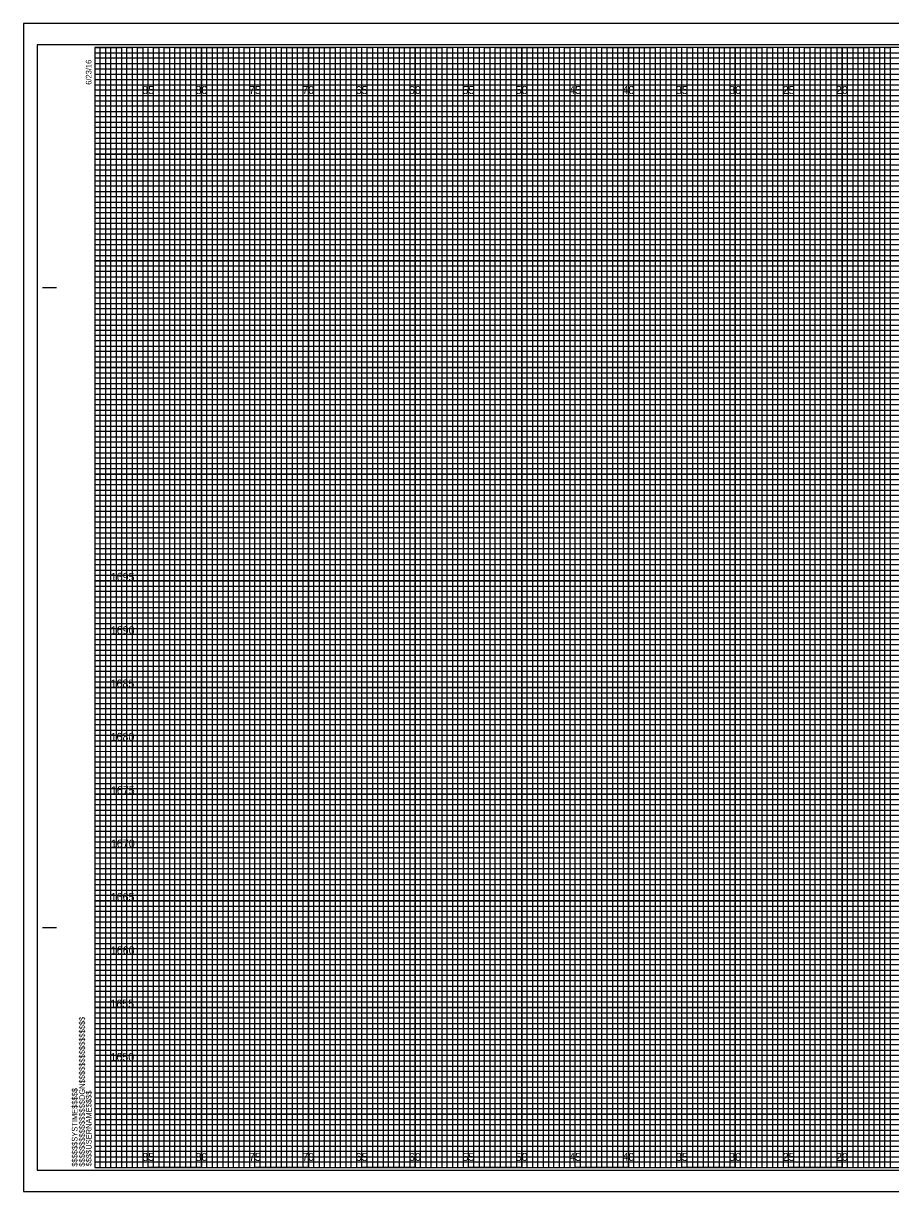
# Model space of a CAD drawing. Extents: x 172 to 723, y -2 to 439.
# Drawn here: x 541.5 to 622.8, y 219.3 to 328.8 of the extents above; entities that cross this region are included whole.
import ezdxf

# ---------------------------------------------------------------- set-up
doc = ezdxf.new("R2010")
doc.units = 0
for name, color, linetype in [('Prop XS Elevation Labels', 7, 'Continuous'), ('Prop XS Offset Labels', 7, 'Continuous'), ('Sheet Cross Section CELL', 7, 'Continuous'), ('Sheet Cross Section Grid Major CELL', 7, 'Continuous'), ('Sheet Cross Section Grid Middle CELL', 7, 'Continuous'), ('Sheet Cross Section Grid Minor 1 CELL', 7, 'Continuous'), ('Sheet Cross Section Grid Minor 2 CELL', 7, 'Continuous'), ('Sheet Cutting Line CELL', 7, 'Continuous'), ('Sheet DOT Grid CELL', 7, 'Continuous'), ('Sheet Plot Border Inside CELL', 7, 'Continuous'), ('Sheet Plot Border Outside CELL', 7, 'Continuous')]:
    doc.layers.add(name, color=color, linetype=linetype)

msp = doc.modelspace()

# ---------------------------------------------------------------- linework, layer by layer
at = {"layer": 'Sheet Cross Section CELL'}
for p, q in [((543.31, 304.07), (544.56, 304.07)), ((543.36, 304.07), (544.61, 304.07)), ((543.31, 244.07), (544.56, 244.07)), ((543.36, 244.07), (544.61, 244.07)), ((548.21, 221.57), (548.21, 221.57)), ((548.21, 221.57), (548.21, 221.57)), ((548.21, 221.57), (548.21, 221.57)), ((548.21, 221.57), (548.21, 221.57)), ((548.21, 221.57), (548.21, 221.57)), ((548.21, 221.57), (548.21, 221.57)), ((548.21, 221.57), (548.21, 221.57))]:
    msp.add_line(p, q, dxfattribs=at)
msp.add_lwpolyline([(708.21, 326.57), (548.21, 326.57), (548.21, 221.57), (708.21, 221.57)], close=True, dxfattribs=at)
at = {"layer": 'Sheet Cross Section Grid Major CELL'}
for p, q in [((553.21, 326.57), (548.21, 326.57)), ((553.21, 221.57), (553.21, 326.57)), ((563.21, 326.57), (558.21, 326.57)), ((558.21, 326.57), (558.21, 221.57)), ((563.21, 221.57), (563.21, 326.57)), ((573.21, 326.57), (568.21, 326.57)), ((568.21, 326.57), (568.21, 221.57)), ((573.21, 221.57), (573.21, 326.57)), ((583.21, 326.57), (578.21, 326.57)), ((578.21, 326.57), (578.21, 221.57)), ((583.21, 221.57), (583.21, 326.57)), ((593.21, 326.57), (588.21, 326.57)), ((588.21, 326.57), (588.21, 221.57)), ((593.21, 221.57), (593.21, 326.57)), ((603.21, 326.57), (598.21, 326.57)), ((598.21, 326.57), (598.21, 221.57)), ((603.21, 221.57), (603.21, 326.57)), ((613.21, 326.57), (608.21, 326.57)), ((608.21, 326.57), (608.21, 221.57)), ((613.21, 221.57), (613.21, 326.57)), ((623.21, 326.57), (618.21, 326.57)), ((618.21, 326.57), (618.21, 221.57)), ((558.21, 221.57), (553.21, 221.57)), ((568.21, 221.57), (563.21, 221.57)), ((578.21, 221.57), (573.21, 221.57)), ((588.21, 221.57), (583.21, 221.57)), ((598.21, 221.57), (593.21, 221.57)), ((608.21, 221.57), (603.21, 221.57)), ((618.21, 221.57), (613.21, 221.57))]:
    msp.add_line(p, q, dxfattribs=at)
for points in [[(548.21, 321.57), (708.21, 321.57), (708.21, 316.57), (548.21, 316.57)], [(548.21, 311.57), (708.21, 311.57), (708.21, 306.57), (548.21, 306.57)], [(548.21, 301.57), (708.21, 301.57), (708.21, 296.57), (548.21, 296.57)], [(548.21, 291.57), (708.21, 291.57), (708.21, 286.57), (548.21, 286.57)], [(548.21, 281.57), (708.21, 281.57), (708.21, 276.57), (548.21, 276.57)], [(548.21, 271.57), (708.21, 271.57), (708.21, 266.57), (548.21, 266.57)], [(548.21, 261.57), (708.21, 261.57), (708.21, 256.57), (548.21, 256.57)], [(548.21, 251.57), (708.21, 251.57), (708.21, 246.57), (548.21, 246.57)], [(548.21, 241.57), (708.21, 241.57), (708.21, 236.57), (548.21, 236.57)], [(548.21, 231.57), (708.21, 231.57), (708.21, 226.57), (548.21, 226.57)]]:
    msp.add_lwpolyline(points, dxfattribs=at)
at = {"layer": 'Sheet Cross Section Grid Middle CELL'}
for points in [[(548.21, 326.57), (550.71, 326.57), (550.71, 221.57), (555.71, 221.57), (555.71, 326.57), (560.71, 326.57), (560.71, 221.57), (565.71, 221.57), (565.71, 326.57), (570.71, 326.57), (570.71, 221.57), (575.71, 221.57), (575.71, 326.57), (580.71, 326.57), (580.71, 221.57), (585.71, 221.57), (585.71, 326.57), (590.71, 326.57), (590.71, 221.57), (595.71, 221.57), (595.71, 326.57), (600.71, 326.57), (600.71, 221.57), (605.71, 221.57), (605.71, 326.57), (610.71, 326.57), (610.71, 221.57), (615.71, 221.57), (615.71, 326.57), (620.71, 326.57), (620.71, 221.57), (625.71, 221.57)], [(548.21, 324.07), (685.71, 324.07)], [(548.21, 314.07), (708.21, 314.07), (708.21, 319.07), (548.21, 319.07)], [(548.21, 304.07), (708.21, 304.07), (708.21, 309.07), (548.21, 309.07)], [(548.21, 294.07), (708.21, 294.07), (708.21, 299.07), (548.21, 299.07)], [(548.21, 284.07), (708.21, 284.07), (708.21, 289.07), (548.21, 289.07)], [(548.21, 274.07), (708.21, 274.07), (708.21, 279.07), (548.21, 279.07)], [(548.21, 264.07), (708.21, 264.07), (708.21, 269.07), (548.21, 269.07)], [(548.21, 254.07), (708.21, 254.07), (708.21, 259.07), (548.21, 259.07)], [(548.21, 244.07), (708.21, 244.07), (708.21, 249.07), (548.21, 249.07)], [(548.21, 234.07), (708.21, 234.07), (708.21, 239.07), (548.21, 239.07)], [(548.21, 224.07), (708.21, 224.07), (708.21, 229.07), (548.21, 229.07)]]:
    msp.add_lwpolyline(points, dxfattribs=at)
at = {"layer": 'Sheet Cross Section Grid Minor 1 CELL'}
for p, q in [((548.21, 326.07), (678.21, 326.07)), ((678.21, 325.56), (548.21, 325.56)), ((548.21, 325.56), (548.21, 325.07)), ((548.21, 325.07), (678.21, 325.07)), ((678.21, 324.52), (548.21, 324.52)), ((548.21, 324.52), (548.21, 323.57)), ((548.21, 323.57), (708.21, 323.57))]:
    msp.add_line(p, q, dxfattribs=at)
for points in [[(548.21, 323.07), (683.21, 323.07), (708.21, 323.07), (708.21, 322.57), (548.21, 322.57)], [(548.21, 322.07), (708.21, 322.07), (708.21, 321.07), (548.21, 321.07)], [(548.21, 320.57), (708.21, 320.57), (708.21, 320.07), (548.21, 320.06)], [(548.21, 319.57), (708.21, 319.57), (708.21, 318.57), (548.21, 318.57)], [(548.21, 318.07), (708.21, 318.07), (708.21, 317.57), (548.21, 317.57)], [(548.21, 317.07), (708.21, 317.07), (708.21, 316.07), (548.21, 316.07)], [(548.21, 315.57), (708.21, 315.57), (708.21, 315.07), (548.21, 315.07)], [(548.21, 314.57), (708.21, 314.57), (708.21, 313.57), (548.21, 313.57)], [(548.21, 313.07), (708.21, 313.07), (708.21, 312.57), (548.21, 312.57)], [(548.21, 312.07), (708.21, 312.07), (708.21, 311.07), (548.21, 311.07)], [(548.21, 310.57), (708.21, 310.57), (708.21, 310.07), (548.21, 310.07)], [(548.21, 309.57), (708.21, 309.57), (708.21, 308.55), (708.21, 308.07), (708.21, 307.57), (548.21, 307.57)], [(548.21, 308.57), (708.21, 308.57), (708.21, 308.07), (548.21, 308.07)], [(548.21, 307.07), (708.21, 307.07), (708.21, 306.07), (548.21, 306.09)], [(548.21, 306.09), (708.21, 306.07), (708.21, 305.57), (548.21, 305.57)], [(548.21, 305.07), (708.21, 305.07), (708.21, 304.57), (548.21, 304.57)], [(548.21, 303.57), (708.21, 303.57), (708.21, 303.07), (548.21, 303.07)], [(548.21, 302.57), (708.21, 302.57), (708.21, 302.07), (548.21, 302.07)], [(548.18, 301.02), (708.21, 301.02), (708.21, 300.51), (548.18, 300.51)], [(548.21, 300.07), (708.21, 300.07), (708.21, 299.57), (548.21, 299.57)], [(548.21, 298.57), (708.21, 298.57), (708.21, 298.07), (548.21, 298.07)], [(548.21, 297.57), (708.21, 297.57), (708.21, 297.07), (548.21, 297.07)], [(548.21, 296.07), (708.21, 296.07), (708.21, 295.57), (548.21, 295.57)], [(548.21, 295.07), (708.21, 295.07), (708.21, 294.57), (548.21, 294.57)], [(548.21, 293.57), (708.21, 293.57), (708.21, 293.07), (548.21, 293.07)], [(548.21, 292.57), (708.21, 292.57), (708.21, 292.07), (548.21, 292.07)], [(548.21, 291.07), (708.21, 291.07), (708.21, 290.56), (548.21, 290.57)], [(548.21, 290.07), (708.21, 290.07), (708.21, 289.57), (548.21, 289.57)], [(548.21, 288.57), (708.21, 288.57), (708.21, 288.07), (548.21, 288.07)], [(548.21, 287.57), (708.21, 287.57), (708.21, 287.07), (548.21, 287.07)], [(548.21, 286.07), (708.21, 286.07), (708.21, 285.57), (548.21, 285.57)], [(548.21, 285.07), (708.21, 285.07), (708.21, 284.57), (548.21, 284.57)], [(548.21, 283.57), (708.21, 283.57), (708.21, 283.07), (548.21, 283.07)], [(548.21, 282.57), (708.21, 282.57), (708.21, 282.07), (548.21, 282.07)], [(548.21, 281.07), (708.21, 281.07), (708.21, 280.57), (548.21, 280.57)], [(548.21, 280.07), (708.25, 280.03), (708.21, 279.57), (548.21, 279.57)], [(548.21, 278.57), (708.21, 278.57), (708.21, 278.07), (548.21, 278.07)], [(548.21, 277.57), (708.21, 277.57), (708.21, 277.07), (548.21, 277.07)], [(548.21, 276.07), (708.21, 276.07), (708.21, 275.57), (548.21, 275.57)], [(548.21, 275.07), (708.21, 275.07), (708.21, 274.57), (548.21, 274.57)], [(548.21, 273.57), (708.21, 273.57), (708.21, 273.07), (548.21, 273.07)], [(548.21, 272.57), (708.21, 272.57), (708.21, 272.07), (548.21, 272.07)], [(548.21, 271.07), (708.21, 271.07), (708.21, 270.57), (548.21, 270.57)], [(548.21, 270.07), (708.21, 270.07), (708.21, 269.57), (548.21, 269.57)], [(548.21, 268.57), (708.21, 268.57), (708.21, 268.07), (548.21, 268.07)], [(548.21, 267.57), (708.21, 267.57), (708.21, 267.07), (548.21, 267.07)], [(548.21, 266.07), (708.21, 266.07), (708.21, 265.57), (548.21, 265.57)], [(548.21, 265.07), (708.21, 265.07), (708.21, 264.57), (548.21, 264.57)], [(548.21, 263.57), (708.21, 263.57), (708.21, 263.07), (548.21, 263.07)], [(548.21, 262.57), (708.21, 262.57), (708.21, 262.07), (548.21, 262.07)], [(548.21, 261.07), (708.21, 261.07), (708.21, 260.56), (548.21, 260.57)], [(548.21, 260.07), (708.21, 260.07), (708.21, 259.57), (548.21, 259.57)], [(548.21, 258.57), (708.21, 258.57), (708.21, 258.07), (548.21, 258.07)], [(548.21, 257.57), (708.21, 257.57), (708.21, 257.07), (548.21, 257.07)], [(548.21, 256.07), (708.21, 256.07), (708.21, 255.57), (548.21, 255.57)], [(548.21, 255.07), (708.21, 255.07), (708.21, 254.57), (548.21, 254.57)], [(548.21, 253.57), (708.21, 253.57), (708.21, 253.07), (548.21, 253.07)], [(548.21, 252.57), (708.21, 252.57), (708.21, 252.07), (548.21, 252.07)], [(548.21, 251.07), (708.21, 251.07), (708.21, 250.57), (548.21, 250.57)], [(548.21, 250.07), (708.25, 250.03), (708.21, 249.57), (548.21, 249.57)], [(548.21, 248.57), (708.21, 248.57), (708.21, 248.07), (548.21, 248.07)], [(548.21, 247.57), (708.21, 247.57), (708.21, 247.07), (548.21, 247.07)], [(548.21, 246.07), (708.21, 246.07), (708.21, 245.57), (548.21, 245.57)], [(548.21, 245.07), (708.21, 245.07), (708.21, 244.57), (548.21, 244.57)], [(548.21, 243.57), (708.21, 243.57), (708.21, 243.07), (548.21, 243.07)], [(548.21, 242.57), (708.21, 242.57), (708.21, 242.07), (548.21, 242.07)], [(548.21, 241.07), (708.21, 241.07), (708.21, 240.57), (548.21, 240.57)], [(548.21, 240.07), (708.21, 240.07), (708.21, 239.57), (548.21, 239.57)], [(548.21, 238.57), (708.21, 238.57), (708.21, 238.07), (548.21, 238.07)], [(548.21, 237.57), (708.21, 237.57), (708.21, 237.07), (548.21, 237.07)], [(548.21, 236.07), (708.21, 236.07), (708.21, 235.57), (548.21, 235.57)], [(548.21, 235.07), (708.21, 235.07), (708.21, 234.57), (548.21, 234.57)], [(548.21, 233.57), (708.21, 233.57), (708.21, 233.07), (548.21, 233.07)], [(548.21, 232.57), (708.21, 232.57), (708.21, 232.07), (548.21, 232.07)], [(548.21, 231.07), (708.21, 231.07), (708.21, 230.57), (548.21, 230.57)], [(548.21, 230.07), (708.21, 230.07), (708.21, 229.57), (548.21, 229.57)], [(548.21, 228.57), (708.21, 228.57), (708.21, 228.07), (548.21, 228.07)], [(548.21, 227.57), (708.21, 227.57), (708.21, 227.07), (548.21, 227.07)], [(548.21, 226.07), (708.21, 226.07), (708.21, 225.57), (548.21, 225.57)], [(548.21, 225.07), (708.21, 225.07), (708.21, 224.57), (548.21, 224.57)], [(548.21, 223.57), (708.21, 223.57), (708.21, 223.07), (548.21, 223.07)], [(548.21, 222.57), (708.21, 222.57), (708.21, 222.07), (548.21, 222.07)]]:
    msp.add_lwpolyline(points, dxfattribs=at)
at = {"layer": 'Sheet Cross Section Grid Minor 2 CELL'}
for points in [[(548.21, 221.57), (548.71, 221.57), (548.71, 326.57), (549.21, 326.57), (549.21, 221.57)], [(549.21, 221.57), (549.71, 221.57), (549.71, 326.57), (550.21, 326.57), (550.21, 221.57)], [(550.71, 221.57), (551.21, 221.57), (551.21, 326.57), (551.71, 326.57), (551.71, 221.57)], [(551.71, 221.57), (552.21, 221.57), (552.21, 326.57), (552.71, 326.57), (552.71, 221.57)], [(553.21, 221.57), (553.71, 221.57), (553.71, 326.57), (554.21, 326.57), (554.21, 221.57)], [(554.21, 221.57), (554.71, 221.57), (554.71, 326.57), (555.21, 326.57), (555.21, 221.57)], [(555.71, 221.57), (556.21, 221.57), (556.21, 326.57), (556.71, 326.57), (556.71, 221.57)], [(556.71, 221.57), (557.21, 221.57), (557.21, 326.57), (557.71, 326.57), (557.71, 221.57)], [(558.21, 221.57), (558.71, 221.57), (558.71, 326.57), (559.21, 326.57), (559.21, 221.57)], [(559.21, 221.57), (559.71, 221.57), (559.71, 326.57), (560.21, 326.57), (560.21, 221.57)], [(560.71, 221.57), (561.21, 221.57), (561.21, 326.57), (561.71, 326.57), (561.71, 221.57)], [(561.71, 221.57), (562.21, 221.57), (562.21, 326.57), (562.71, 326.57), (562.71, 221.57)], [(563.21, 221.57), (563.71, 221.57), (563.71, 326.57), (564.21, 326.57), (564.21, 221.57)], [(564.21, 221.57), (564.71, 221.57), (564.71, 326.57), (565.21, 326.57), (565.21, 221.57)], [(565.71, 221.57), (566.21, 221.57), (566.21, 326.57), (566.71, 326.57), (566.71, 221.57)], [(566.71, 221.57), (567.21, 221.57), (567.21, 326.57), (567.71, 326.57), (567.71, 221.57)], [(568.21, 221.57), (568.71, 221.57), (568.71, 326.57), (569.21, 326.57), (569.21, 221.57)], [(569.21, 221.57), (569.71, 221.57), (569.71, 326.57), (570.21, 326.57), (570.21, 221.57)], [(570.71, 221.57), (571.21, 221.57), (571.21, 326.57), (571.71, 326.57), (571.71, 221.57)], [(571.71, 221.57), (572.21, 221.57), (572.21, 326.57), (572.71, 326.57), (572.71, 221.57)], [(573.21, 221.57), (573.71, 221.57), (573.71, 326.57), (574.21, 326.57), (574.21, 221.57)], [(574.21, 221.57), (574.71, 221.57), (574.71, 326.57), (575.21, 326.57), (575.21, 221.57)], [(575.71, 221.57), (576.21, 221.57), (576.21, 326.57), (576.71, 326.57), (576.71, 221.57)], [(576.71, 221.57), (577.21, 221.57), (577.21, 326.57), (577.71, 326.57), (577.71, 221.57)], [(578.21, 221.57), (578.71, 221.57), (578.71, 326.57), (579.21, 326.57), (579.21, 221.57)], [(579.21, 221.57), (579.71, 221.57), (579.71, 326.57), (580.21, 326.57), (580.21, 221.57)], [(580.71, 221.57), (581.21, 221.57), (581.21, 326.57), (581.71, 326.57), (581.71, 221.57)], [(581.71, 221.57), (582.21, 221.57), (582.21, 326.57), (582.71, 326.57), (582.71, 221.57)], [(583.21, 221.57), (583.71, 221.57), (583.71, 326.57), (584.21, 326.57), (584.21, 221.57)], [(584.21, 221.57), (584.71, 221.57), (584.71, 326.57), (585.21, 326.57), (585.21, 221.57)], [(585.71, 221.57), (586.21, 221.57), (586.21, 326.57), (586.71, 326.57), (586.71, 221.57)], [(586.71, 221.57), (587.21, 221.57), (587.21, 326.57), (587.71, 326.57), (587.71, 221.57)], [(588.21, 221.57), (588.71, 221.57), (588.71, 326.57), (589.21, 326.57), (589.21, 221.57)], [(589.21, 221.57), (589.71, 221.57), (589.71, 326.57), (590.21, 326.57), (590.21, 221.57)], [(590.71, 221.57), (591.21, 221.57), (591.21, 326.57), (591.71, 326.57), (591.71, 221.57)], [(591.71, 221.57), (592.21, 221.57), (592.21, 326.57), (592.71, 326.57), (592.71, 221.57)], [(593.21, 221.57), (593.71, 221.57), (593.71, 326.57), (594.21, 326.57), (594.21, 221.57)], [(594.21, 221.57), (594.71, 221.57), (594.71, 326.57), (595.21, 326.57), (595.21, 221.57)], [(595.71, 221.57), (596.21, 221.57), (596.21, 326.57), (596.71, 326.57), (596.71, 221.57)], [(596.71, 221.57), (597.21, 221.57), (597.21, 326.57), (597.71, 326.57), (597.71, 221.57)], [(598.21, 221.57), (598.71, 221.57), (598.71, 326.57), (599.21, 326.57), (599.21, 221.57)], [(599.21, 221.57), (599.71, 221.57), (599.71, 326.57), (600.21, 326.57), (600.21, 221.57)], [(600.71, 221.57), (601.21, 221.57), (601.21, 326.57), (601.71, 326.57), (601.71, 221.57)], [(601.71, 221.57), (602.21, 221.57), (602.21, 326.57), (602.71, 326.57), (602.71, 221.57)], [(603.21, 221.57), (603.71, 221.57), (603.71, 326.57), (604.21, 326.57), (604.21, 221.57)], [(604.21, 221.57), (604.71, 221.57), (604.71, 326.57), (605.21, 326.57), (605.21, 221.57)], [(605.71, 221.57), (606.21, 221.57), (606.21, 326.57), (606.71, 326.57), (606.71, 221.57)], [(606.71, 221.57), (607.21, 221.57), (607.21, 326.57), (607.71, 326.57), (607.71, 221.57)], [(608.21, 221.57), (608.71, 221.57), (608.71, 326.57), (609.21, 326.57), (609.21, 221.57)], [(609.21, 221.57), (609.71, 221.57), (609.71, 326.57), (610.21, 326.57), (610.21, 221.57)], [(610.71, 221.57), (611.21, 221.57), (611.21, 326.57), (611.71, 326.57), (611.71, 221.57)], [(611.71, 221.57), (612.21, 221.57), (612.21, 326.57), (612.71, 326.57), (612.71, 221.57)], [(613.21, 221.57), (613.71, 221.57), (613.71, 326.57), (614.21, 326.57), (614.21, 221.57)], [(614.21, 221.57), (614.71, 221.57), (614.71, 326.57), (615.21, 326.57), (615.21, 221.57)], [(615.71, 221.57), (616.21, 221.57), (616.21, 326.57), (616.71, 326.57), (616.71, 221.57)], [(616.71, 221.57), (617.21, 221.57), (617.21, 326.57), (617.71, 326.57), (617.71, 221.57)], [(618.21, 221.57), (618.71, 221.57), (618.71, 326.57), (619.21, 326.57), (619.21, 221.57)], [(619.21, 221.57), (619.71, 221.57), (619.71, 326.57), (620.21, 326.57), (620.21, 221.57)], [(620.71, 221.57), (621.21, 221.57), (621.21, 326.57), (621.71, 326.57), (621.71, 221.57)], [(621.71, 221.57), (622.21, 221.57), (622.21, 326.57), (622.71, 326.57), (622.71, 221.57)]]:
    msp.add_lwpolyline(points, dxfattribs=at)
at = {"layer": 'Sheet Cutting Line CELL'}
for p, q in [((709.86, 328.82), (541.51, 328.82)), ((541.51, 328.82), (541.51, 219.32)), ((541.51, 219.32), (709.86, 219.32))]:
    msp.add_line(p, q, dxfattribs=at)
at = {"layer": 'Sheet DOT Grid CELL'}
for p, q in [((553.21, 221.57), (553.21, 326.57)), ((558.21, 221.57), (558.21, 326.57)), ((563.21, 221.57), (563.21, 326.57)), ((568.21, 221.57), (568.21, 326.57)), ((573.21, 221.57), (573.21, 326.57)), ((578.21, 221.57), (578.21, 326.57)), ((583.21, 221.57), (583.21, 326.57)), ((588.21, 221.57), (588.21, 326.57)), ((593.21, 221.57), (593.21, 326.57)), ((598.21, 221.57), (598.21, 326.57)), ((603.21, 221.57), (603.21, 326.57)), ((608.21, 221.57), (608.21, 326.57)), ((613.21, 221.57), (613.21, 326.57)), ((618.21, 221.57), (618.21, 326.57)), ((548.21, 321.57), (708.21, 321.57)), ((548.21, 316.57), (708.21, 316.57)), ((548.21, 311.57), (708.21, 311.57)), ((548.21, 306.57), (708.21, 306.57)), ((548.21, 301.57), (708.21, 301.57)), ((548.21, 296.57), (708.21, 296.57)), ((548.21, 291.57), (708.21, 291.57)), ((548.21, 286.57), (708.21, 286.57)), ((548.21, 281.57), (708.21, 281.57)), ((548.21, 276.57), (708.21, 276.57)), ((548.21, 271.57), (708.21, 271.57)), ((548.21, 266.57), (708.21, 266.57)), ((548.21, 261.57), (708.21, 261.57)), ((548.21, 256.57), (708.21, 256.57)), ((548.21, 251.57), (708.21, 251.57)), ((548.21, 246.57), (708.21, 246.57)), ((548.21, 241.57), (708.21, 241.57)), ((548.21, 236.57), (708.21, 236.57)), ((548.21, 231.57), (708.21, 231.57)), ((548.21, 226.57), (708.21, 226.57))]:
    msp.add_line(p, q, dxfattribs=at)
at = {"layer": 'Sheet Plot Border Inside CELL'}
msp.add_lwpolyline([(542.81, 221.32), (709.41, 221.32), (709.41, 326.82), (542.81, 326.82)], close=True, dxfattribs=at)
at = {"layer": 'Sheet Plot Border Outside CELL'}
msp.add_lwpolyline([(541.51, 219.32), (709.86, 219.32), (709.86, 328.82), (541.51, 328.82)], close=True, dxfattribs=at)

# ---------------------------------------------------------------- texts
at = {"layer": 'Prop XS Elevation Labels'}
for s, p in [('1695', (549.69, 276.57)), ('1690', (549.7, 271.57)), ('1685', (549.68, 266.57)), ('1680', (549.68, 261.57)), ('1675', (549.71, 256.57)), ('1670', (549.71, 251.57)), ('1665', (549.69, 246.57)), ('1660', (549.7, 241.57)), ('1655', (549.66, 236.57)), ('1650', (549.67, 231.57))]:
    msp.add_text(s, height=0.75, dxfattribs=at).set_placement(p)
at = {"layer": 'Prop XS Offset Labels'}
for s, p in [('85', (552.65, 322.2)), ('80', (557.64, 322.2)), ('75', (562.65, 322.2)), ('70', (567.64, 322.2)), ('65', (572.65, 322.2)), ('60', (577.64, 322.2)), ('55', (582.65, 322.2)), ('50', (587.64, 322.2)), ('45', (592.65, 322.2)), ('40', (597.64, 322.2)), ('35', (602.65, 322.2)), ('30', (607.64, 322.2)), ('25', (612.65, 322.2)), ('20', (617.64, 322.2)), ('85', (552.65, 222.2)), ('80', (557.64, 222.2)), ('75', (562.65, 222.2)), ('70', (567.64, 222.2)), ('65', (572.65, 222.2)), ('60', (577.64, 222.2)), ('55', (582.65, 222.2)), ('50', (587.64, 222.2)), ('45', (592.65, 222.2)), ('40', (597.64, 222.2)), ('35', (602.65, 222.2)), ('30', (607.64, 222.2)), ('25', (612.65, 222.2)), ('20', (617.64, 222.2))]:
    msp.add_text(s, height=0.75, dxfattribs=at).set_placement(p)
at = {"layer": 'Sheet Cross Section CELL'}
for s, p in [('6/23/16', (547.89, 323.07)), ('$$$$$$$$$$$$$$$$DGN$$$$$$$$$$$$$$$$', (547.27, 221.66)), ('$$$$$$SYSTIME$$$$$', (546.58, 221.66)), ('$$$$USERNAME$$$$', (547.9, 221.69))]:
    msp.add_text(s, height=0.525, rotation=90, dxfattribs=at).set_placement(p)

doc.saveas('drawing.dxf')
